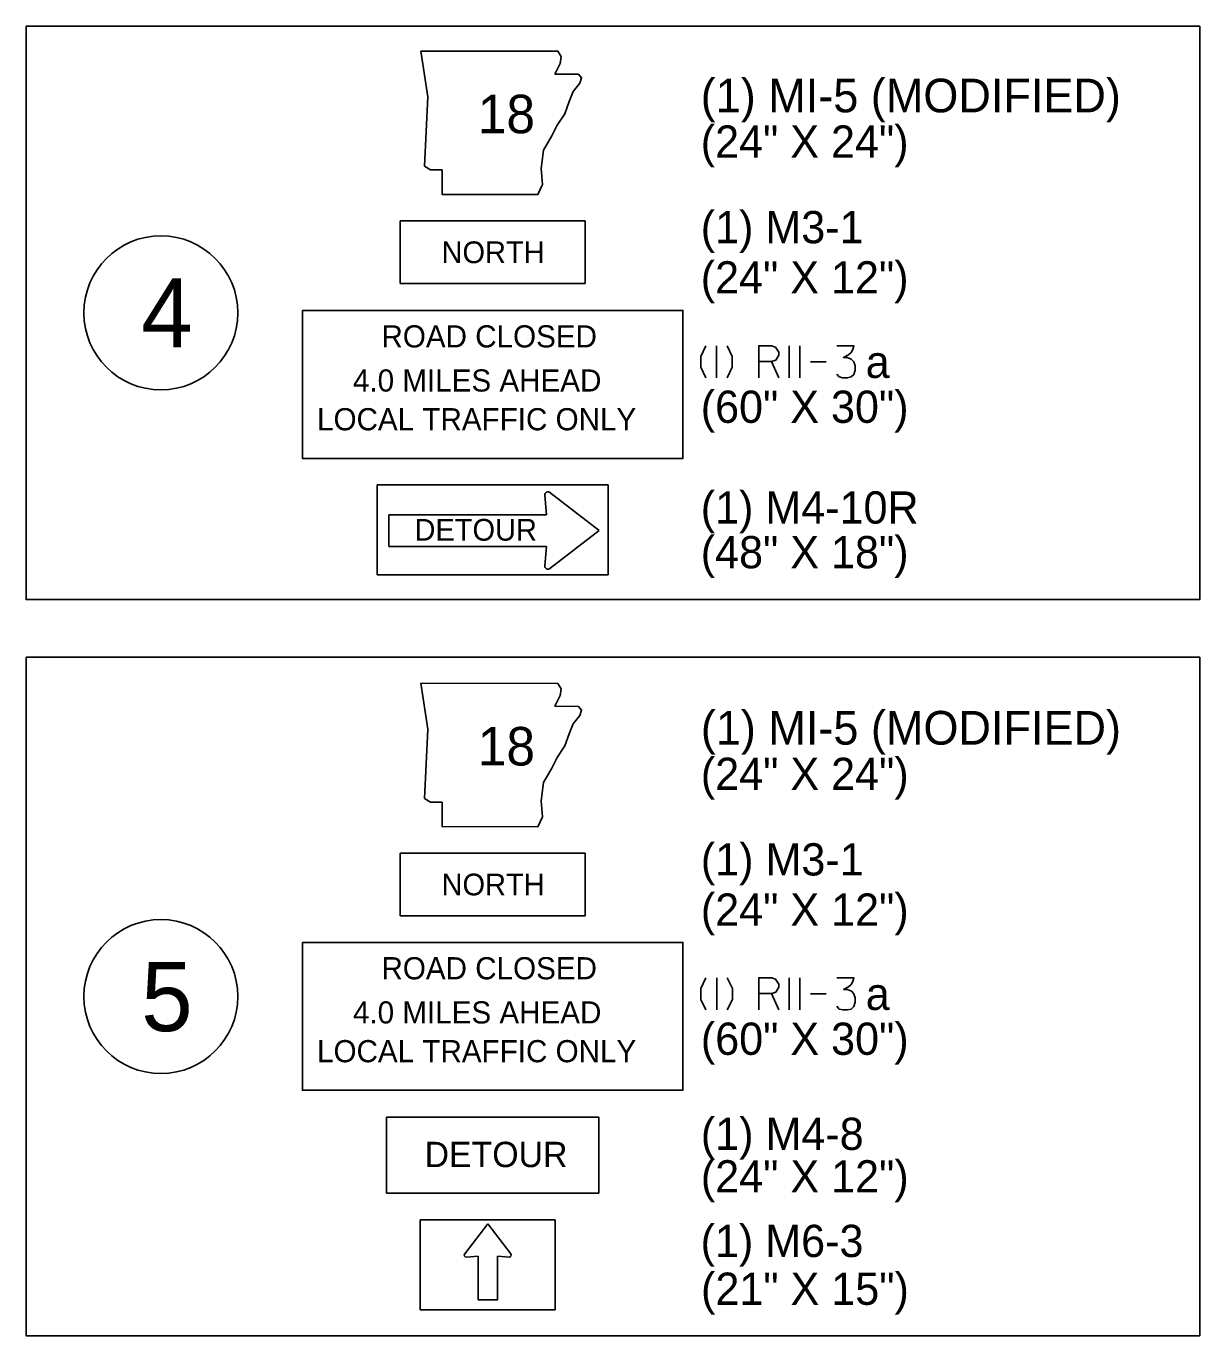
# Model space of a CAD drawing. Extents: x -31818 to 1228740, y -23925 to 152440.
# Drawn here: x -31809.4 to -31789.07, y -23871.4 to -23848.72 of the extents above; entities that cross this region are included whole.
import ezdxf

# ---------------------------------------------------------------- set-up
doc = ezdxf.new("R2010")
doc.units = 0
for name, color, linetype in [('21', 7, 'Continuous'), ('3', 7, 'Continuous'), ('59', 7, 'Continuous'), ('8', 7, 'Continuous'), ('Level 1', 7, 'Continuous'), ('Level 3', 7, 'Continuous'), ('Level 8', 7, 'Continuous'), ('shading', 7, 'Continuous')]:
    doc.layers.add(name, color=color, linetype=linetype)

msp = doc.modelspace()

# ---------------------------------------------------------------- linework, layer by layer
at = {"layer": '21'}
for points in [[(-31802.563, -23849.152), (-31802.445, -23849.944), (-31802.499, -23851.145), (-31802.394, -23851.211), (-31802.196, -23851.211), (-31802.196, -23851.634), (-31800.534, -23851.635), (-31800.454, -23851.464), (-31800.481, -23851.187), (-31800.441, -23850.87), (-31800.295, -23850.619), (-31800.203, -23850.435), (-31800.07, -23850.237), (-31799.991, -23850.026), (-31799.925, -23849.854), (-31799.806, -23849.709), (-31799.779, -23849.617), (-31799.832, -23849.551), (-31800.242, -23849.551), (-31800.149, -23849.366), (-31800.135, -23849.247), (-31800.19, -23849.156)], [(-31802.563, -23860.101), (-31802.445, -23860.893), (-31802.499, -23862.094), (-31802.394, -23862.16), (-31802.196, -23862.16), (-31802.196, -23862.582), (-31800.534, -23862.584), (-31800.454, -23862.412), (-31800.481, -23862.135), (-31800.441, -23861.819), (-31800.295, -23861.568), (-31800.203, -23861.383), (-31800.07, -23861.186), (-31799.991, -23860.975), (-31799.925, -23860.803), (-31799.806, -23860.658), (-31799.779, -23860.566), (-31799.832, -23860.5), (-31800.242, -23860.499), (-31800.149, -23860.315), (-31800.135, -23860.196), (-31800.19, -23860.105)]]:
    msp.add_lwpolyline(points, close=True, dxfattribs=at)
at = {"layer": '3'}
for centre, radius, start, end in [((-31800.359, -23856.842), 0.055, 52.3853, 184.5739), ((-31800.359, -23858.07), 0.055, 175.4261, 307.6112), ((-31801.777, -23870.003), 0.0334, 142.3888, 274.5739), ((-31801.031, -23870.003), 0.0334, 265.4261, 37.6147)]:
    msp.add_arc(centre, radius, start, end, dxfattribs=at)
at = {"layer": '59'}
for p, q in [((-31799.719, -23852.094), (-31802.92, -23852.094)), ((-31802.92, -23852.094), (-31802.92, -23853.18)), ((-31799.719, -23852.094), (-31799.719, -23853.18)), ((-31799.719, -23853.18), (-31802.92, -23853.18)), ((-31799.316, -23856.665), (-31803.323, -23856.665)), ((-31803.323, -23856.665), (-31803.323, -23858.222)), ((-31799.316, -23856.665), (-31799.316, -23858.222)), ((-31800.414, -23856.846), (-31800.387, -23857.181)), ((-31800.326, -23856.798), (-31799.472, -23857.456)), ((-31800.387, -23857.181), (-31803.121, -23857.181)), ((-31803.121, -23857.181), (-31803.121, -23857.731)), ((-31799.472, -23857.456), (-31800.326, -23858.114)), ((-31800.387, -23857.731), (-31803.121, -23857.731)), ((-31800.387, -23857.731), (-31800.414, -23858.066)), ((-31799.316, -23858.222), (-31803.323, -23858.222)), ((-31799.719, -23863.042), (-31802.92, -23863.042)), ((-31802.92, -23863.042), (-31802.92, -23864.129)), ((-31799.719, -23863.042), (-31799.719, -23864.128)), ((-31799.719, -23864.128), (-31802.92, -23864.129)), ((-31799.482, -23867.612), (-31803.157, -23867.612)), ((-31803.157, -23867.612), (-31803.157, -23868.929)), ((-31799.482, -23867.612), (-31799.482, -23868.928)), ((-31799.482, -23868.928), (-31803.157, -23868.929)), ((-31800.234, -23869.392), (-31802.574, -23869.392)), ((-31802.574, -23869.392), (-31802.574, -23870.95)), ((-31801.404, -23869.464), (-31801.803, -23869.982)), ((-31801.004, -23869.982), (-31801.404, -23869.464)), ((-31800.234, -23869.392), (-31800.234, -23870.95)), ((-31801.571, -23870.02), (-31801.774, -23870.036)), ((-31801.571, -23870.02), (-31801.571, -23870.779)), ((-31801.033, -23870.036), (-31801.237, -23870.02)), ((-31800.234, -23870.95), (-31802.574, -23870.95))]:
    msp.add_line(p, q, dxfattribs=at)
msp.add_lwpolyline([(-31801.237, -23870.02), (-31801.237, -23870.779), (-31801.571, -23870.779)], dxfattribs=at)
at = {"layer": '8'}
for points in [[(-31809.402, -23848.722), (-31789.067, -23848.722), (-31789.067, -23858.651), (-31809.402, -23858.651)], [(-31809.402, -23859.651), (-31789.067, -23859.651), (-31789.067, -23871.4), (-31809.402, -23871.4)]]:
    msp.add_lwpolyline(points, close=True, dxfattribs=at)
at = {"layer": 'Level 1'}
for points in [[(-31804.615, -23853.645), (-31798.024, -23853.645), (-31798.024, -23856.206), (-31804.615, -23856.206)], [(-31804.615, -23864.587), (-31798.024, -23864.587), (-31798.024, -23867.148), (-31804.615, -23867.148)]]:
    msp.add_lwpolyline(points, close=True, dxfattribs=at)
at = {"layer": 'Level 8'}
for p, q in [((-31797.44, -23854.814), (-31797.44, -23854.256)), ((-31796.182, -23854.814), (-31796.182, -23854.256)), ((-31795.998, -23854.814), (-31795.998, -23854.256)), ((-31796.49, -23854.528), (-31796.363, -23854.814)), ((-31795.813, -23854.533), (-31795.541, -23854.533)), ((-31797.438, -23865.758), (-31797.438, -23865.2)), ((-31796.181, -23865.758), (-31796.181, -23865.2)), ((-31795.996, -23865.758), (-31795.996, -23865.2)), ((-31796.489, -23865.473), (-31796.361, -23865.758)), ((-31795.812, -23865.477), (-31795.539, -23865.477))]:
    msp.add_line(p, q, dxfattribs=at)
for points in [[(-31797.624, -23854.256), (-31797.712, -23854.44), (-31797.712, -23854.629), (-31797.624, -23854.814)], [(-31797.255, -23854.256), (-31797.167, -23854.44), (-31797.167, -23854.629), (-31797.255, -23854.814)], [(-31796.71, -23854.814), (-31796.71, -23854.256), (-31796.486, -23854.256), (-31796.42, -23854.278), (-31796.363, -23854.365), (-31796.363, -23854.418), (-31796.415, -23854.506), (-31796.486, -23854.528), (-31796.71, -23854.528)], [(-31795.356, -23854.256), (-31795.061, -23854.256), (-31795.079, -23854.322), (-31795.11, -23854.37), (-31795.154, -23854.414), (-31795.242, -23854.458), (-31795.176, -23854.458), (-31795.105, -23854.489), (-31795.061, -23854.533), (-31795.039, -23854.603), (-31795.039, -23854.678), (-31795.061, -23854.752), (-31795.11, -23854.796), (-31795.176, -23854.814), (-31795.25, -23854.814), (-31795.316, -23854.796), (-31795.356, -23854.748)], [(-31797.623, -23865.2), (-31797.711, -23865.385), (-31797.711, -23865.574), (-31797.623, -23865.758)], [(-31797.254, -23865.2), (-31797.166, -23865.385), (-31797.166, -23865.574), (-31797.254, -23865.758)], [(-31796.709, -23865.758), (-31796.709, -23865.2), (-31796.484, -23865.2), (-31796.418, -23865.222), (-31796.361, -23865.31), (-31796.361, -23865.363), (-31796.414, -23865.451), (-31796.484, -23865.473), (-31796.709, -23865.473)], [(-31795.355, -23865.2), (-31795.06, -23865.2), (-31795.078, -23865.266), (-31795.108, -23865.314), (-31795.152, -23865.358), (-31795.24, -23865.402), (-31795.174, -23865.402), (-31795.104, -23865.433), (-31795.06, -23865.477), (-31795.038, -23865.547), (-31795.038, -23865.622), (-31795.06, -23865.697), (-31795.108, -23865.741), (-31795.174, -23865.758), (-31795.249, -23865.758), (-31795.315, -23865.741), (-31795.355, -23865.693)]]:
    msp.add_lwpolyline(points, dxfattribs=at)
for centre in [(-31807.068, -23853.686), (-31807.068, -23865.525)]:
    msp.add_circle(centre, 1.333, dxfattribs=at)
at = {"layer": 'shading'}
for centre in [(-31807.068, -23853.686), (-31807.068, -23865.525)]:
    msp.add_circle(centre, 1.333, dxfattribs=at)

# ---------------------------------------------------------------- texts
at = {"layer": '3'}
for s, height, p in [('NORTH', 0.3759, (-31802.205, -23852.825)), ('DETOUR', 0.3759, (-31802.674, -23857.631)), ('NORTH', 0.3759, (-31802.205, -23863.773)), ('DETOUR', 0.4386, (-31802.499, -23868.479))]:
    msp.add_text(s, height=height, rotation=360, dxfattribs=at).set_placement(p)
at = {"layer": '8'}
for p in [(-31801.577, -23850.576), (-31801.577, -23861.524)]:
    msp.add_text('18', height=0.667, dxfattribs=at).set_placement(p)
at = {"layer": 'Level 1'}
for p in [(-31803.74, -23855.049), (-31803.74, -23865.992)]:
    msp.add_text('4.0 MILES AHEAD', height=0.38362, dxfattribs=at).set_placement(p)
at = {"layer": 'Level 3'}
for s, p in [('ROAD CLOSED', (-31803.246, -23854.285)), ('LOCAL TRAFFIC ONLY', (-31804.362, -23855.72)), ('ROAD CLOSED', (-31803.246, -23865.227)), ('LOCAL TRAFFIC ONLY', (-31804.362, -23866.663))]:
    msp.add_text(s, height=0.38363, dxfattribs=at).set_placement(p)
at = {"layer": 'Level 8'}
for s, height, rotation, p in [('(1) MI-5 (MODIFIED)', 0.58333, 360, (-31797.714, -23850.214)), ('(24" X 24")', 0.55832, 0, (-31797.714, -23850.999)), ('(1) M3-1', 0.5583, 0, (-31797.714, -23852.481)), ('(24" X 12")', 0.55832, 0, (-31797.714, -23853.351)), ('(1) M4-10R', 0.5583, 0, (-31797.714, -23857.336)), ('(48" X 18")', 0.55832, 0, (-31797.714, -23858.109)), ('(1) MI-5 (MODIFIED)', 0.58333, 360, (-31797.712, -23861.163)), ('(24" X 24")', 0.55832, 0, (-31797.712, -23861.948)), ('(1) M3-1', 0.5583, 0, (-31797.712, -23863.429)), ('(24" X 12")', 0.55832, 0, (-31797.712, -23864.299)), ('(1) M4-8', 0.5583, 360, (-31797.712, -23868.181)), ('(24" X 12")', 0.55832, 360, (-31797.712, -23868.918)), ('(1) M6-3', 0.5583, 360, (-31797.716, -23870.036)), ('(21" X 15")', 0.55832, 360, (-31797.709, -23870.864))]:
    msp.add_text(s, height=height, rotation=rotation, dxfattribs=at).set_placement(p)
for s, height, p in [('4', 1.2, (-31807.409, -23854.286)), ('a', 0.558, (-31794.856, -23854.814)), ('(60" X 30")', 0.55829, (-31797.714, -23855.591)), ('5', 1.2, (-31807.409, -23866.125)), ('a', 0.558, (-31794.855, -23865.758)), ('(60" X 30")', 0.55829, (-31797.712, -23866.535))]:
    msp.add_text(s, height=height, dxfattribs=at).set_placement(p)

doc.saveas('drawing.dxf')
